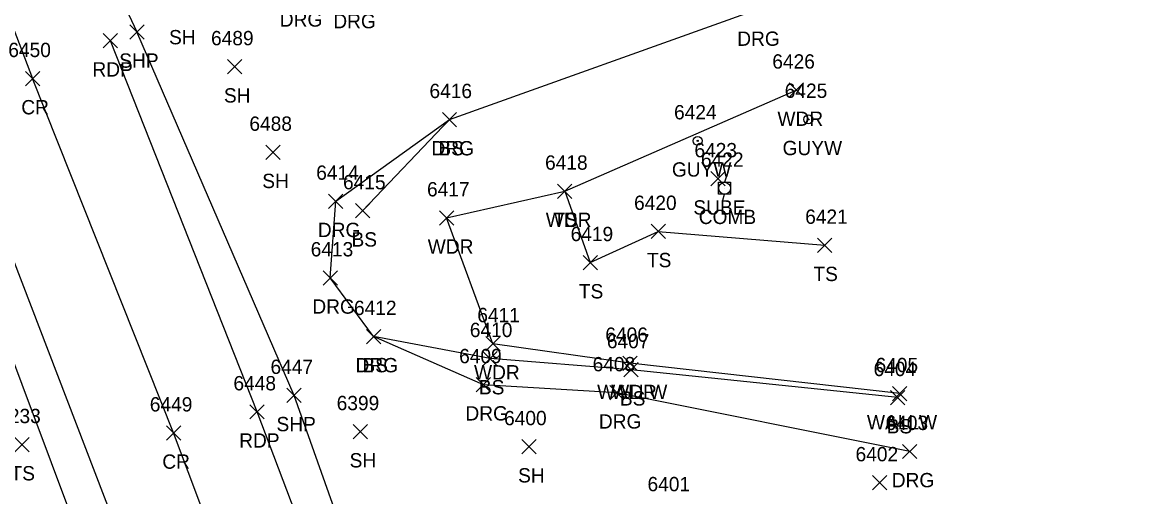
# Model space of a CAD drawing. Extents: x 1769141 to 1770817, y 735471 to 742405.
# Drawn here: x 1770229.2 to 1770384.3, y 740677.5 to 740743.8 of the extents above; entities that cross this region are included whole.
import ezdxf

# ---------------------------------------------------------------- set-up
doc = ezdxf.new("R2010")
doc.units = 0
for name, color, linetype in [('L_A', 7, 'Continuous'), ('L_I', 7, 'Continuous'), ('L_TIC', 7, 'Continuous'), ('LAWA', 7, 'Continuous'), ('LELB', 7, 'Continuous'), ('LW', 7, 'Continuous'), ('P_A', 7, 'Continuous'), ('P_I', 7, 'Continuous'), ('P_TIC', 7, 'Continuous'), ('PET', 7, 'Continuous'), ('PRC', 7, 'Continuous'), ('PSP', 7, 'Continuous'), ('R_A', 7, 'Continuous'), ('R_I', 7, 'Continuous'), ('R_TIC', 7, 'Continuous'), ('RDG', 7, 'Continuous'), ('U_A', 7, 'Continuous'), ('U_I', 7, 'Continuous'), ('U_TIC', 7, 'Continuous'), ('UP', 7, 'Continuous'), ('UPGW', 7, 'Continuous')]:
    doc.layers.add(name, color=color, linetype=linetype)

msp = doc.modelspace()

# ---------------------------------------------------------------- linework, layer by layer
at = {"layer": 'L_TIC'}
for points in [[(1770257.95, 740736.56), (1770259.95, 740738.56)], [(1770259.95, 740736.56), (1770257.95, 740738.56)], [(1770336.45, 740733.3), (1770338.45, 740735.3)], [(1770338.45, 740733.3), (1770336.45, 740735.3)], [(1770287.97, 740729.18), (1770289.97, 740731.18)], [(1770289.97, 740729.18), (1770287.97, 740731.18)], [(1770263.31, 740724.61), (1770265.31, 740726.61)], [(1770265.31, 740724.61), (1770263.31, 740726.61)], [(1770304.07, 740719.18), (1770306.07, 740721.18)], [(1770306.07, 740719.18), (1770304.07, 740721.18)], [(1770304.07, 740719.18), (1770306.07, 740721.18)], [(1770306.07, 740719.18), (1770304.07, 740721.18)], [(1770275.83, 740716.44), (1770277.83, 740718.44)], [(1770277.83, 740716.44), (1770275.83, 740718.44)], [(1770287.57, 740715.45), (1770289.57, 740717.45)], [(1770289.57, 740715.45), (1770287.57, 740717.45)], [(1770317.16, 740713.56), (1770319.16, 740715.56)], [(1770319.16, 740713.56), (1770317.16, 740715.56)], [(1770340.43, 740711.62), (1770342.43, 740713.62)], [(1770342.43, 740711.62), (1770340.43, 740713.62)], [(1770307.64, 740709.2), (1770309.64, 740711.2)], [(1770309.64, 740709.2), (1770307.64, 740711.2)], [(1770277.36, 740698.88), (1770279.36, 740700.88)], [(1770279.36, 740698.88), (1770277.36, 740700.88)], [(1770294.04, 740697.88), (1770296.04, 740699.88)], [(1770296.04, 740697.88), (1770294.04, 740699.88)], [(1770293.64, 740695.8), (1770295.64, 740697.8)], [(1770295.64, 740695.8), (1770293.64, 740697.8)], [(1770313.2, 740695.14), (1770315.2, 740697.14)], [(1770315.2, 740695.14), (1770313.2, 740697.14)], [(1770313.2, 740695.14), (1770315.2, 740697.14)], [(1770315.2, 740695.14), (1770313.2, 740697.14)], [(1770313.35, 740694.24), (1770315.35, 740696.24)], [(1770315.35, 740694.24), (1770313.35, 740696.24)], [(1770350.63, 740690.35), (1770352.63, 740692.35)], [(1770352.63, 740690.35), (1770350.63, 740692.35)], [(1770350.9, 740690.9), (1770352.9, 740692.9)], [(1770352.9, 740690.9), (1770350.9, 740692.9)], [(1770275.52, 740685.59), (1770277.52, 740687.59)], [(1770277.52, 740685.59), (1770275.52, 740687.59)], [(1770228.2, 740683.78), (1770230.2, 740685.78)], [(1770230.2, 740683.78), (1770228.2, 740685.78)], [(1770299.08, 740683.49), (1770301.08, 740685.49)], [(1770301.08, 740683.49), (1770299.08, 740685.49)], [(1770348.12, 740678.45), (1770350.12, 740680.45)], [(1770350.12, 740678.45), (1770348.12, 740680.45)]]:
    msp.add_lwpolyline(points, dxfattribs=at)
at = {"layer": 'LAWA'}
msp.add_lwpolyline([(1770314.2, 740696.14), (1770295.04, 740698.88), (1770288.57, 740716.45), (1770305.07, 740720.18), (1770337.45, 740734.3)], dxfattribs=at)
at = {"layer": 'LELB'}
for points in [[(1770276.83, 740717.44), (1770288.97, 740730.18)], [(1770305.07, 740720.18), (1770308.64, 740710.2), (1770318.16, 740714.56), (1770341.43, 740712.62)], [(1770351.63, 740691.35), (1770314.35, 740695.24), (1770294.64, 740696.8), (1770278.36, 740699.88)]]:
    msp.add_lwpolyline(points, dxfattribs=at)
at = {"layer": 'LW'}
msp.add_lwpolyline([(1770351.9, 740691.9), (1770314.2, 740696.14)], dxfattribs=at)
at = {"layer": 'P_TIC'}
for points in [[(1770244.28, 740741.42), (1770246.28, 740743.42)], [(1770246.28, 740741.42), (1770244.28, 740743.42)], [(1770240.57, 740740.19), (1770242.57, 740742.19)], [(1770242.57, 740740.19), (1770240.57, 740742.19)], [(1770229.69, 740734.91), (1770231.69, 740736.91)], [(1770231.69, 740734.91), (1770229.69, 740736.91)], [(1770266.25, 740690.65), (1770268.25, 740692.65)], [(1770268.25, 740690.65), (1770266.25, 740692.65)], [(1770261.08, 740688.36), (1770263.08, 740690.36)], [(1770263.08, 740688.36), (1770261.08, 740690.36)], [(1770249.4, 740685.41), (1770251.4, 740687.41)], [(1770251.4, 740685.41), (1770249.4, 740687.41)]]:
    msp.add_lwpolyline(points, dxfattribs=at)
at = {"layer": 'PET'}
for points in [[(1770234.49, 740765.32), (1770245.28, 740742.42)], [(1770379.16, 740373.29), (1770360.22, 740424.51), (1770338.77, 740482.71), (1770320.68, 740531.7), (1770305.06, 740574.76), (1770283.59, 740632.55), (1770262.08, 740689.36), (1770241.57, 740741.19)], [(1770354.08, 740371.38), (1770337.26, 740416.85), (1770319.32, 740465.72), (1770304.6, 740505.64), (1770288.87, 740548.76), (1770274.11, 740588.9), (1770250.94, 740650.86), (1770225.28, 740717.64)]]:
    msp.add_lwpolyline(points, dxfattribs=at)
at = {"layer": 'PRC'}
for points in [[(1770221.59, 740759.67), (1770230.69, 740735.91)], [(1770366.94, 740369.74), (1770348.35, 740420.63), (1770327.06, 740479.58), (1770309.33, 740527.72), (1770293.48, 740571.26), (1770272.53, 740627.61), (1770250.4, 740686.41), (1770230.69, 740735.91)]]:
    msp.add_lwpolyline(points, dxfattribs=at)
at = {"layer": 'PSP'}
for points in [[(1770384.34, 740374.74), (1770365.93, 740426.73), (1770363, 740434.14), (1770343.37, 740484.07), (1770326.57, 740533.85), (1770310.21, 740576.26), (1770285.85, 740639.32), (1770267.25, 740691.65), (1770245.28, 740742.42)], [(1770346.98, 740368.28), (1770329.75, 740414.99), (1770313.12, 740462.55), (1770298.15, 740502.39), (1770298.12, 740506.76), (1770283.52, 740546.61), (1770275.49, 740567.79), (1770273.86, 740568.65), (1770259.2, 740607.52), (1770260.25, 740609.6), (1770245.76, 740649.04), (1770220.84, 740715.43)]]:
    msp.add_lwpolyline(points, dxfattribs=at)
at = {"layer": 'R_TIC'}
for points in [[(1770287.97, 740729.18), (1770289.97, 740731.18)], [(1770289.97, 740729.18), (1770287.97, 740731.18)], [(1770272.08, 740717.77), (1770274.08, 740719.77)], [(1770274.08, 740717.77), (1770272.08, 740719.77)], [(1770271.31, 740707.07), (1770273.31, 740709.07)], [(1770273.31, 740707.07), (1770271.31, 740709.07)], [(1770277.36, 740698.88), (1770279.36, 740700.88)], [(1770279.36, 740698.88), (1770277.36, 740700.88)], [(1770292.71, 740692.15), (1770294.71, 740694.15)], [(1770294.71, 740692.15), (1770292.71, 740694.15)], [(1770311.36, 740691.02), (1770313.36, 740693.02)], [(1770313.36, 740691.02), (1770311.36, 740693.02)], [(1770352.3, 740682.82), (1770354.3, 740684.82)], [(1770354.3, 740682.82), (1770352.3, 740684.82)]]:
    msp.add_lwpolyline(points, dxfattribs=at)
at = {"layer": 'RDG'}
msp.add_lwpolyline([(1770353.3, 740683.82), (1770312.36, 740692.02), (1770293.71, 740693.15), (1770278.36, 740699.88), (1770272.31, 740708.07), (1770273.08, 740718.77), (1770288.97, 740730.18), (1770331.7, 740745.48)], dxfattribs=at)
at = {"layer": 'U_TIC'}
for points in [[(1770325.52, 740720.91), (1770327.52, 740722.91)], [(1770327.52, 740720.91), (1770325.52, 740722.91)]]:
    msp.add_lwpolyline(points, dxfattribs=at)
at = {"layer": 'UP'}
for p, q in [((1770326.59, 740719.76), (1770326.59, 740721.43)), ((1770326.59, 740721.43), (1770328.26, 740721.43)), ((1770327.68, 740722.26), (1770327.43, 740721.43)), ((1770328.26, 740721.43), (1770328.26, 740719.76)), ((1770328.26, 740719.76), (1770326.59, 740719.76)), ((1770327.18, 740718.93), (1770327.43, 740719.76)), ((1770327.43, 740720.59), (1770327.43, 740720.59))]:
    msp.add_line(p, q, dxfattribs=at)
msp.add_circle((1770327.43, 740720.59), 0.833, dxfattribs=at)
at = {"layer": 'UPGW'}
for centre, radius in [((1770339.14, 740730.21), 0.625), ((1770339.14, 740730.21), 0.0833), ((1770323.66, 740727.21), 0.625), ((1770323.66, 740727.21), 0.0833)]:
    msp.add_circle(centre, radius, dxfattribs=at)

# ---------------------------------------------------------------- texts
at = {"layer": 'L_A'}
for s, p in [('SH', (1770249.77, 740740.69)), ('SH', (1770257.44, 740732.56)), ('WDR', (1770334.81, 740729.3)), ('BS', (1770287.41, 740725.18)), ('SH', (1770262.8, 740720.61)), ('WDR', (1770302.43, 740715.18)), ('TS', (1770303.48, 740715.18)), ('BS', (1770275.27, 740712.44)), ('WDR', (1770285.93, 740711.45)), ('TS', (1770316.57, 740709.56)), ('TS', (1770339.84, 740707.62)), ('TS', (1770307.05, 740705.2)), ('BS', (1770276.8, 740694.88)), ('WDR', (1770292.4, 740693.88)), ('BS', (1770293.08, 740691.8)), ('WALLW', (1770309.61, 740691.14)), ('WDR', (1770311.56, 740691.14)), ('BS', (1770312.79, 740690.24)), ('WALLW', (1770347.32, 740686.9)), ('BS', (1770350.08, 740686.35)), ('SH', (1770275.01, 740681.59)), ('TS', (1770227.61, 740679.78)), ('SH', (1770298.56, 740679.49))]:
    msp.add_text(s, height=2, dxfattribs=at).set_placement(p)
at = {"layer": 'L_I'}
for s, p in [('6489', (1770255.64, 740740.56)), ('6426', (1770334.09, 740737.3)), ('6416', (1770286.17, 740733.18)), ('6488', (1770261, 740728.61)), ('6418', (1770302.33, 740723.18)), ('6418', (1770302.33, 740723.18)), ('6415', (1770274.09, 740720.44)), ('6417', (1770285.83, 740719.45)), ('6420', (1770314.77, 740717.56)), ('6421', (1770338.69, 740715.62)), ('6419', (1770305.9, 740713.2)), ('6412', (1770275.62, 740702.88)), ('6411', (1770292.86, 740701.88)), ('6410', (1770291.81, 740699.8)), ('6406', (1770310.75, 740699.14)), ('6406', (1770310.75, 740699.14)), ('6407', (1770310.97, 740698.24)), ('6404', (1770348.25, 740694.35)), ('6405', (1770348.52, 740694.9)), ('6399', (1770273.2, 740689.59)), ('6233', (1770225.89, 740687.78)), ('6400', (1770296.6, 740687.49)), ('6402', (1770345.73, 740682.45)), ('6401', (1770316.65, 740678.27))]:
    msp.add_text(s, height=2, dxfattribs=at).set_placement(p)
at = {"layer": 'P_A'}
for s, p in [('RDP', (1770239.06, 740736.19)), ('SHP', (1770242.81, 740737.42)), ('CR', (1770229.12, 740730.91)), ('SHP', (1770264.79, 740686.65)), ('RDP', (1770259.57, 740684.36)), ('CR', (1770248.83, 740681.41))]:
    msp.add_text(s, height=2, dxfattribs=at).set_placement(p)
at = {"layer": 'P_I'}
for s, p in [('6450', (1770227.3, 740738.91)), ('6447', (1770263.95, 740694.65)), ('6448', (1770258.77, 740692.36)), ('6449', (1770247.08, 740689.41))]:
    msp.add_text(s, height=2, dxfattribs=at).set_placement(p)
at = {"layer": 'R_A'}
for p in [(1770265.25, 740743.16), (1770272.73, 740742.93), (1770329.19, 740740.48), (1770286.45, 740725.18), (1770270.57, 740713.77), (1770269.8, 740703.07), (1770275.84, 740694.88), (1770291.2, 740688.15), (1770309.85, 740687.02), (1770350.79, 740678.82)]:
    msp.add_text('DRG', height=2, dxfattribs=at).set_placement(p)
at = {"layer": 'R_I'}
for s, p in [('6416', (1770286.17, 740733.18)), ('6414', (1770270.34, 740721.77)), ('6413', (1770269.57, 740711.07)), ('6412', (1770275.62, 740702.88)), ('6409', (1770290.32, 740696.15)), ('6408', (1770308.98, 740695.02)), ('6403', (1770349.92, 740686.82))]:
    msp.add_text(s, height=2, dxfattribs=at).set_placement(p)
at = {"layer": 'U_A'}
for s, p in [('GUYW', (1770335.53, 740725.21)), ('GUYW', (1770320.06, 740722.21)), ('SUBE', (1770323.06, 740716.91)), ('COMB', (1770323.81, 740715.59))]:
    msp.add_text(s, height=2, dxfattribs=at).set_placement(p)
at = {"layer": 'U_I'}
for s, p in [('6425', (1770335.83, 740733.21)), ('6424', (1770320.36, 740730.21)), ('6423', (1770323.21, 740724.91)), ('6422', (1770324.12, 740723.59))]:
    msp.add_text(s, height=2, dxfattribs=at).set_placement(p)

doc.saveas('drawing.dxf')
